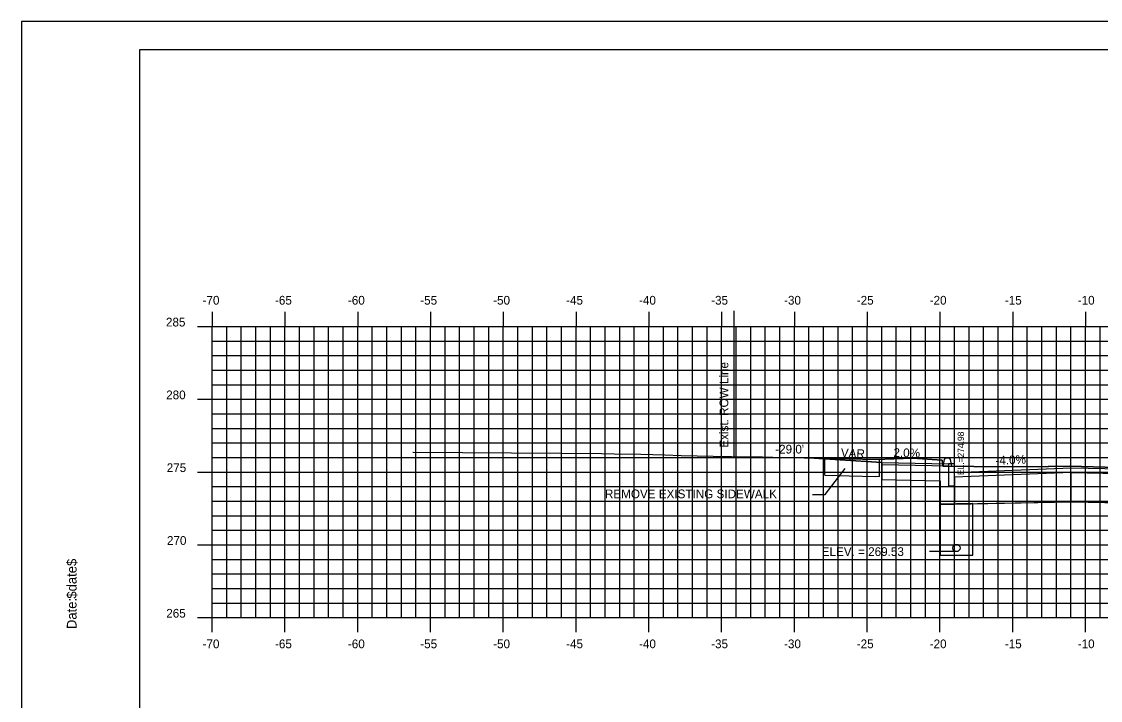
# Model space of a CAD drawing. Extents: x 854231 to 854401, y 366268 to 366378.
# Drawn here: x 854230.7 to 854304.8, y 366331.6 to 366378.2 of the extents above; entities that cross this region are included whole.
import ezdxf

# ---------------------------------------------------------------- set-up
doc = ezdxf.new("R2010")
doc.units = 0
for name, color, linetype in [('ANNOTATION', 7, 'Continuous'), ('BORDER', 7, 'Continuous'), ('D_Curb_Type_1_Lt', 7, 'Continuous'), ('D_Roadway_Edge_TW', 7, 'Continuous'), ('D_Roadway_FinishedGrade', 7, 'Continuous'), ('D_Roadway_Sidewalks_Paved', 7, 'Continuous'), ('D_Roadway_SubGrade', 7, 'Continuous'), ('D_Text_Standard', 7, 'Continuous'), ('E_ROW_Line', 7, 'Continuous'), ('H_V ANNOTATION', 7, 'Continuous'), ('JUNK COM EXC', 7, 'Continuous'), ('junk strct exc', 7, 'Continuous'), ('MAJOR', 7, 'Continuous'), ('MINOR', 7, 'Continuous'), ('PDRAIN', 7, 'Continuous'), ('PLOT BOUNDARY', 7, 'Continuous'), ('S_Curb_Type_3', 7, 'Continuous'), ('S_Roadway_Centerline', 7, 'Continuous')]:
    doc.layers.add(name, color=color, linetype=linetype)

msp = doc.modelspace()

# ---------------------------------------------------------------- linework, layer by layer
at = {"layer": 'ANNOTATION'}
msp.add_lwpolyline([(854285.012, 366345.69), (854285.894, 366345.69), (854287.248, 366347.486)], dxfattribs=at)
at = {"layer": 'BORDER'}
for p, q in [((854398.771, 366376.236), (854238.771, 366376.236)), ((854238.771, 366376.236), (854238.771, 366271.236))]:
    msp.add_line(p, q, dxfattribs=at)
at = {"layer": 'D_Curb_Type_1_Lt'}
msp.add_lwpolyline([(854294.359, 366347.799), (854294.359, 366346.299), (854294.776, 366346.299), (854294.776, 366347.799)], close=True, dxfattribs=at)
at = {"layer": 'D_Roadway_Edge_TW'}
msp.add_lwpolyline([(854294.775, 366347.215), (854302.775, 366347.535), (854324.775, 366347.095), (854332.771, 366346.775)], dxfattribs=at)
at = {"layer": 'D_Roadway_FinishedGrade'}
msp.add_line((854289.771, 366347.89), (854284.771, 366348.205), dxfattribs=at)
at = {"layer": 'D_Roadway_Sidewalks_Paved'}
msp.add_lwpolyline([(854289.771, 366347.89), (854294.359, 366347.799), (854294.359, 366347.632), (854289.771, 366347.724)], close=True, dxfattribs=at)
at = {"layer": 'D_Roadway_SubGrade'}
msp.add_lwpolyline([(854289.771, 366347.724), (854289.771, 366346.723), (854293.776, 366346.643), (854293.776, 366345.022), (854294.776, 366345.042)], dxfattribs=at)
for points in [[(854302.775, 366347.202), (854294.775, 366346.882), (854294.775, 366345.042), (854302.775, 366345.202)], [(854302.775, 366345.202), (854302.775, 366347.202), (854313.775, 366346.982), (854324.775, 366346.762), (854324.775, 366344.762), (854313.775, 366344.982)]]:
    msp.add_lwpolyline(points, close=True, dxfattribs=at)
at = {"layer": 'D_Text_Standard'}
msp.add_lwpolyline([(854294.901, 366341.771), (854293.722, 366341.771), (854293.042, 366341.771)], dxfattribs=at)
at = {"layer": 'E_ROW_Line'}
msp.add_line((854279.629, 366348.31), (854279.629, 366358.31), dxfattribs=at)
at = {"layer": 'JUNK COM EXC'}
msp.add_lwpolyline([(854309.962, 366347.434), (854302.686, 366347.633), (854301.229, 366347.612), (854301.205, 366347.614), (854298.226, 366347.585), (854293.964, 366347.644), (854293.947, 366347.863), (854293.929, 366348.054), (854291.885, 366348.18), (854289.343, 366348.103), (854284.771, 366348.205), (854287.271, 366348.048), (854289.771, 366347.89), (854289.771, 366346.723), (854293.776, 366346.643), (854293.776, 366345.022), (854302.775, 366345.202), (854324.775, 366344.762)], dxfattribs=at)
at = {"layer": 'junk strct exc'}
msp.add_lwpolyline([(854293.776, 366345.022), (854293.776, 366341.521), (854296.026, 366341.521), (854296.026, 366345.067)], close=True, dxfattribs=at)
at = {"layer": 'MAJOR'}
for p, q in [((854243.771, 366358.238), (854243.771, 366357.236)), ((854248.771, 366358.238), (854248.771, 366357.236)), ((854253.771, 366358.238), (854253.771, 366357.236)), ((854258.771, 366358.238), (854258.771, 366357.236)), ((854263.771, 366358.238), (854263.771, 366357.236)), ((854268.771, 366358.238), (854268.771, 366357.236)), ((854273.771, 366358.238), (854273.771, 366357.236)), ((854278.771, 366358.238), (854278.771, 366357.236)), ((854283.771, 366358.238), (854283.771, 366357.236)), ((854288.771, 366358.238), (854288.771, 366357.236)), ((854293.771, 366358.238), (854293.771, 366357.236)), ((854298.771, 366358.238), (854298.771, 366357.236)), ((854303.771, 366358.238), (854303.771, 366357.236)), ((854242.769, 366357.236), (854243.771, 366357.236)), ((854243.771, 366357.236), (854383.771, 366357.236)), ((854243.771, 366337.236), (854243.771, 366357.236)), ((854243.771, 366337.236), (854243.771, 366357.236)), ((854243.771, 366357.236), (854383.771, 366357.236)), ((854248.771, 366337.236), (854248.771, 366357.236)), ((854253.771, 366337.236), (854253.771, 366357.236)), ((854258.771, 366337.236), (854258.771, 366357.236)), ((854263.771, 366337.236), (854263.771, 366357.236)), ((854268.771, 366337.236), (854268.771, 366357.236)), ((854273.771, 366337.236), (854273.771, 366357.236)), ((854278.771, 366337.236), (854278.771, 366357.236)), ((854283.771, 366337.236), (854283.771, 366357.236)), ((854288.771, 366337.236), (854288.771, 366357.236)), ((854293.771, 366337.236), (854293.771, 366357.236)), ((854298.771, 366337.236), (854298.771, 366357.236)), ((854303.771, 366337.236), (854303.771, 366357.236)), ((854242.769, 366352.236), (854243.771, 366352.236)), ((854243.771, 366352.236), (854383.771, 366352.236)), ((854242.769, 366347.236), (854243.771, 366347.236)), ((854243.771, 366347.236), (854383.771, 366347.236)), ((854242.769, 366342.236), (854243.771, 366342.236)), ((854243.771, 366342.236), (854383.771, 366342.236)), ((854242.769, 366337.236), (854243.771, 366337.236)), ((854243.771, 366337.236), (854383.771, 366337.236)), ((854243.771, 366337.236), (854383.771, 366337.236)), ((854243.771, 366336.234), (854243.771, 366337.236)), ((854248.771, 366336.234), (854248.771, 366337.236)), ((854253.771, 366336.234), (854253.771, 366337.236)), ((854258.771, 366336.234), (854258.771, 366337.236)), ((854263.771, 366336.234), (854263.771, 366337.236)), ((854268.771, 366336.234), (854268.771, 366337.236)), ((854273.771, 366336.234), (854273.771, 366337.236)), ((854278.771, 366336.234), (854278.771, 366337.236)), ((854283.771, 366336.234), (854283.771, 366337.236)), ((854288.771, 366336.234), (854288.771, 366337.236)), ((854293.771, 366336.234), (854293.771, 366337.236)), ((854298.771, 366336.234), (854298.771, 366337.236)), ((854303.771, 366336.234), (854303.771, 366337.236))]:
    msp.add_line(p, q, dxfattribs=at)
at = {"layer": 'MINOR'}
for p, q in [((854244.771, 366337.236), (854244.771, 366357.236)), ((854245.771, 366337.236), (854245.771, 366357.236)), ((854246.771, 366337.236), (854246.771, 366357.236)), ((854247.771, 366337.236), (854247.771, 366357.236)), ((854249.771, 366337.236), (854249.771, 366357.236)), ((854250.771, 366337.236), (854250.771, 366357.236)), ((854251.771, 366337.236), (854251.771, 366357.236)), ((854252.771, 366337.236), (854252.771, 366357.236)), ((854254.771, 366337.236), (854254.771, 366357.236)), ((854255.771, 366337.236), (854255.771, 366357.236)), ((854256.771, 366337.236), (854256.771, 366357.236)), ((854257.771, 366337.236), (854257.771, 366357.236)), ((854259.771, 366337.236), (854259.771, 366357.236)), ((854260.771, 366337.236), (854260.771, 366357.236)), ((854261.771, 366337.236), (854261.771, 366357.236)), ((854262.771, 366337.236), (854262.771, 366357.236)), ((854264.771, 366337.236), (854264.771, 366357.236)), ((854265.771, 366337.236), (854265.771, 366357.236)), ((854266.771, 366337.236), (854266.771, 366357.236)), ((854267.771, 366337.236), (854267.771, 366357.236)), ((854269.771, 366337.236), (854269.771, 366357.236)), ((854270.771, 366337.236), (854270.771, 366357.236)), ((854271.771, 366337.236), (854271.771, 366357.236)), ((854272.771, 366337.236), (854272.771, 366357.236)), ((854274.771, 366337.236), (854274.771, 366357.236)), ((854275.771, 366337.236), (854275.771, 366357.236)), ((854276.771, 366337.236), (854276.771, 366357.236)), ((854277.771, 366337.236), (854277.771, 366357.236)), ((854279.771, 366337.236), (854279.771, 366357.236)), ((854280.771, 366337.236), (854280.771, 366357.236)), ((854281.771, 366337.236), (854281.771, 366357.236)), ((854282.771, 366337.236), (854282.771, 366357.236)), ((854284.771, 366337.236), (854284.771, 366357.236)), ((854285.771, 366337.236), (854285.771, 366357.236)), ((854286.771, 366337.236), (854286.771, 366357.236)), ((854287.771, 366337.236), (854287.771, 366357.236)), ((854289.771, 366337.236), (854289.771, 366357.236)), ((854290.771, 366337.236), (854290.771, 366357.236)), ((854291.771, 366337.236), (854291.771, 366357.236)), ((854292.771, 366337.236), (854292.771, 366357.236)), ((854294.771, 366337.236), (854294.771, 366357.236)), ((854295.771, 366337.236), (854295.771, 366357.236)), ((854296.771, 366337.236), (854296.771, 366357.236)), ((854297.771, 366337.236), (854297.771, 366357.236)), ((854299.771, 366337.236), (854299.771, 366357.236)), ((854300.771, 366337.236), (854300.771, 366357.236)), ((854301.771, 366337.236), (854301.771, 366357.236)), ((854302.771, 366337.236), (854302.771, 366357.236)), ((854304.771, 366337.236), (854304.771, 366357.236)), ((854243.771, 366356.236), (854383.771, 366356.236)), ((854243.771, 366356.236), (854244.773, 366356.236)), ((854243.771, 366355.236), (854383.771, 366355.236)), ((854243.771, 366355.236), (854244.773, 366355.236)), ((854243.771, 366354.236), (854383.771, 366354.236)), ((854243.771, 366354.236), (854244.773, 366354.236)), ((854243.771, 366353.236), (854383.771, 366353.236)), ((854243.771, 366353.236), (854244.773, 366353.236)), ((854243.771, 366351.236), (854383.771, 366351.236)), ((854243.771, 366351.236), (854244.773, 366351.236)), ((854243.771, 366350.236), (854383.771, 366350.236)), ((854243.771, 366350.236), (854244.773, 366350.236)), ((854243.771, 366349.236), (854383.771, 366349.236)), ((854243.771, 366349.236), (854244.773, 366349.236)), ((854243.771, 366348.236), (854383.771, 366348.236)), ((854243.771, 366348.236), (854244.773, 366348.236)), ((854243.771, 366346.236), (854383.771, 366346.236)), ((854243.771, 366346.236), (854244.773, 366346.236)), ((854243.771, 366345.236), (854383.771, 366345.236)), ((854243.771, 366345.236), (854244.773, 366345.236)), ((854243.771, 366344.236), (854383.771, 366344.236)), ((854243.771, 366344.236), (854244.773, 366344.236)), ((854243.771, 366343.236), (854383.771, 366343.236)), ((854243.771, 366343.236), (854244.773, 366343.236)), ((854243.771, 366341.236), (854383.771, 366341.236)), ((854243.771, 366341.236), (854244.773, 366341.236)), ((854243.771, 366340.236), (854383.771, 366340.236)), ((854243.771, 366340.236), (854244.773, 366340.236)), ((854243.771, 366339.236), (854383.771, 366339.236)), ((854243.771, 366339.236), (854244.773, 366339.236)), ((854243.771, 366338.236), (854383.771, 366338.236)), ((854243.771, 366338.236), (854244.773, 366338.236))]:
    msp.add_line(p, q, dxfattribs=at)
at = {"layer": 'PDRAIN'}
msp.add_lwpolyline([(854293.776, 366345.022), (854293.776, 366341.521), (854296.026, 366341.521), (854296.026, 366345.022)], dxfattribs=at)
msp.add_circle((854294.901, 366342.021), 0.25, dxfattribs=at)
at = {"layer": 'PLOT BOUNDARY'}
msp.add_lwpolyline([(854230.678, 366268.177), (854400.678, 366268.177), (854400.678, 366378.177), (854230.678, 366378.177)], close=True, dxfattribs=at)
at = {"layer": 'S_Curb_Type_3'}
for points in [[(854294.066, 366348.088), (854293.964, 366347.644), (854294.589, 366347.644), (854294.486, 366348.088)], [(854294.364, 366348.185), (854294.188, 366348.185)]]:
    msp.add_lwpolyline(points, dxfattribs=at)
for centre, start, end in [((854294.188, 366348.06), 90, 167.00538), ((854294.364, 366348.06), 12.99462, 90)]:
    msp.add_arc(centre, 0.125, start, end, dxfattribs=at)
at = {"layer": 'S_Roadway_Centerline'}
for p, q in [((854285.852, 366347.016), (854285.852, 366348.183)), ((854289.621, 366346.93), (854289.621, 366348.112))]:
    msp.add_line(p, q, dxfattribs=at)
for points in [[(854257.56, 366348.593), (854257.576, 366348.601), (854267.72, 366348.525), (854270.514, 366348.504), (854271.399, 366348.496), (854273.217, 366348.474), (854274.875, 366348.409), (854275.994, 366348.374), (854278.195, 366348.329), (854279.446, 366348.313), (854281.579, 366348.28), (854283.018, 366348.24), (854285.838, 366348.184), (854287.558, 366348.144), (854289.343, 366348.103), (854291.885, 366348.18), (854293.929, 366348.054), (854293.947, 366347.863), (854293.964, 366347.644), (854298.226, 366347.585), (854301.205, 366347.614), (854301.229, 366347.612), (854302.686, 366347.633), (854309.962, 366347.434)], [(854285.852, 366347.016), (854287.532, 366346.978), (854289.347, 366346.936), (854289.621, 366346.944)]]:
    msp.add_lwpolyline(points, dxfattribs=at)

# ---------------------------------------------------------------- texts
at = {"layer": 'ANNOTATION'}
for s, rotation, p in [('VAR.', 356.91769, (854286.948, 366348.272)), ('2.0%', 358.85424, (854290.569, 366348.275)), ('-4.0%', 2.29061, (854297.592, 366347.729))]:
    msp.add_text(s, height=0.6, rotation=rotation, dxfattribs=at).set_placement(p)
at = {"layer": 'BORDER'}
for s, p in [('$date$', (854234.456, 366338.542)), ('Date:', (854234.456, 366336.453))]:
    msp.add_text(s, height=0.6696, rotation=90, dxfattribs=at).set_placement(p)
at = {"layer": 'D_Text_Standard'}
msp.add_text(' EL.=274.98', height=0.4335, rotation=90, dxfattribs=at).set_placement((854295.419, 366346.869))
for s, p in [("-29.0'", (854282.453, 366348.509)), ('REMOVE EXISTING SIDEWALK', (854270.755, 366345.436)), ('ELEV. = 269.53', (854285.648, 366341.471))]:
    msp.add_text(s, height=0.6, dxfattribs=at).set_placement(p)
at = {"layer": 'E_ROW_Line'}
msp.add_text('Exist. ROW Line', height=0.6, rotation=90, dxfattribs=at).set_placement((854279.229, 366348.91))
at = {"layer": 'H_V ANNOTATION'}
for s, p in [('-70', (854243.112, 366358.736)), ('-65', (854248.088, 366358.736)), ('-60', (854253.096, 366358.736)), ('-50', (854263.075, 366358.736)), ('-40', (854273.096, 366358.736)), ('-35', (854278.051, 366358.736)), ('-30', (854283.059, 366358.736)), ('-25', (854288.056, 366358.736)), ('-20', (854293.064, 366358.736)), ('-10', (854303.236, 366358.736)), ('-55', (854258.067, 366358.736)), ('-45', (854268.088, 366358.736)), ('-15', (854298.228, 366358.736)), ('285', (854240.595, 366357.236)), ('280', (854240.611, 366352.236)), ('275', (854240.649, 366347.236)), ('270', (854240.665, 366342.236)), ('265', (854240.617, 366337.236)), ('-70', (854243.112, 366335.136)), ('-65', (854248.088, 366335.136)), ('-60', (854253.096, 366335.136)), ('-55', (854258.067, 366335.136)), ('-50', (854263.075, 366335.136)), ('-45', (854268.088, 366335.136)), ('-40', (854273.096, 366335.136)), ('-35', (854278.051, 366335.136)), ('-30', (854283.059, 366335.136)), ('-25', (854288.056, 366335.136)), ('-20', (854293.064, 366335.136)), ('-15', (854298.228, 366335.136)), ('-10', (854303.236, 366335.136))]:
    msp.add_text(s, height=0.6, dxfattribs=at).set_placement(p)

doc.saveas('drawing.dxf')
